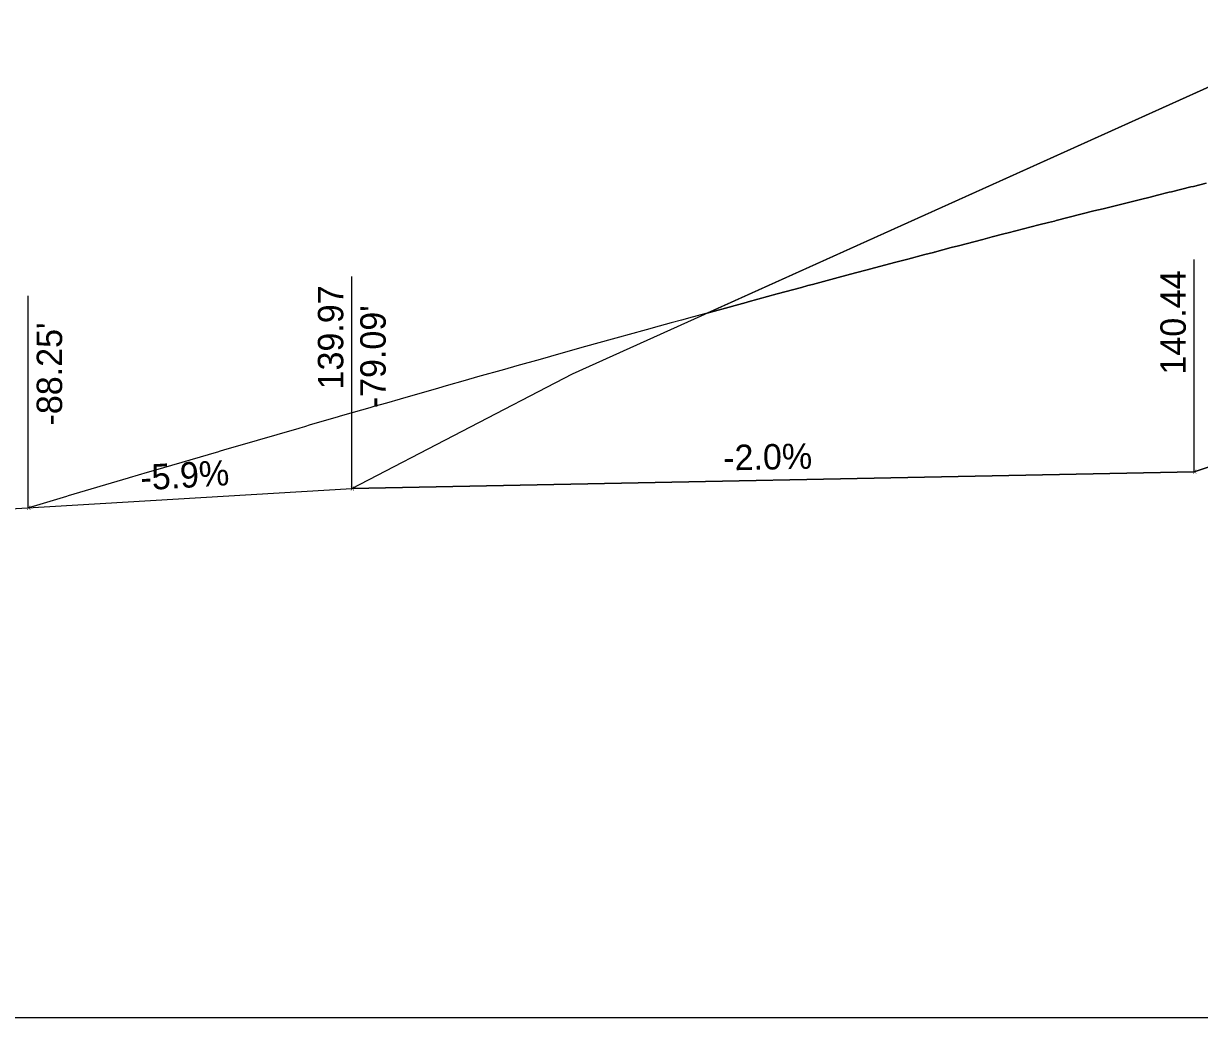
# Model space of a CAD drawing. Extents: x -26 to 4403, y -13 to 9578.
# Drawn here: x 3161.62 to 3194.9, y 8500 to 8528.12 of the extents above; entities that cross this region are included whole.
import ezdxf

# ---------------------------------------------------------------- set-up
doc = ezdxf.new("R2010")
doc.units = 0
for name, color, linetype in [('DTM_CONTOURS_MINOR', 7, 'Continuous'), ('DTM_X_GROUND', 7, 'Continuous'), ('X_PROFILES_1', 7, 'Continuous'), ('XS_CELL', 7, 'Continuous'), ('XS_M_SHAPES_EARTHWORK', 7, 'Continuous'), ('XS_P_GROUND', 7, 'Continuous'), ('XS_P_TX_CLEARZONE', 7, 'Continuous'), ('XS_P_TX_FS_BS', 7, 'Continuous')]:
    doc.layers.add(name, color=color, linetype=linetype)

msp = doc.modelspace()

# ---------------------------------------------------------------- linework, layer by layer
at = {"layer": 'DTM_X_GROUND'}
msp.add_lwpolyline([(3153.808, 8513.95), (3170.909, 8514.966), (3177.153, 8518.209), (3197.118, 8527.209), (3198.789, 8527.5), (3201.713, 8527.882), (3210.312, 8528.066), (3213.777, 8528.123), (3216.864, 8528.039), (3224.572, 8527.826), (3225.877, 8527.605), (3229.562, 8526.928), (3236.992, 8522.323), (3249.998, 8515.154), (3250, 8515.153), (3250.751, 8515.018), (3252.885, 8514.328), (3255.752, 8514.055), (3262.783, 8513.146), (3270.679, 8512.757), (3325.754, 8511.013), (3363.759, 8510.776), (3378.096, 8510.765), (3400, 8511.068)], dxfattribs=at)
at = {"layer": 'XS_CELL'}
msp.add_line((3000, 8500), (3250, 8500), dxfattribs=at)
at = {"layer": 'XS_M_SHAPES_EARTHWORK'}
msp.add_lwpolyline([(3170.909, 8514.966), (3177.153, 8518.209), (3197.118, 8527.209), (3198.789, 8527.5), (3201.713, 8527.882), (3210.312, 8528.066), (3213.777, 8528.123), (3216.864, 8528.039), (3224.572, 8527.826), (3225.877, 8527.605), (3229.562, 8526.928), (3231.967, 8525.437), (3225.826, 8525.314), (3220, 8523.858), (3194.753, 8515.443)], close=True, dxfattribs=at)
at = {"layer": 'XS_P_GROUND'}
msp.add_line((3180.966, 8519.928), (3181.279, 8520.011), dxfattribs=at)
for points in [[(3229.815, 8526.77), (3229.562, 8526.928), (3225.877, 8527.605), (3224.572, 8527.826), (3216.864, 8528.039), (3213.777, 8528.123), (3210.312, 8528.066), (3201.713, 8527.882), (3198.789, 8527.5), (3197.118, 8527.209), (3180.966, 8519.928)], [(3194.753, 8515.443), (3220, 8523.858), (3220, 8523.858), (3220, 8523.858), (3232, 8526.858)], [(3195.088, 8523.603), (3194.732, 8523.516), (3194.659, 8523.499), (3194.104, 8523.362), (3194.046, 8523.349), (3193.671, 8523.255), (3193.641, 8523.248), (3193.468, 8523.205), (3193.266, 8523.158), (3192.171, 8522.882), (3191.914, 8522.82), (3190.845, 8522.547), (3190.796, 8522.535), (3190.628, 8522.491), (3190.354, 8522.425), (3189.483, 8522.198), (3189.363, 8522.169), (3189.037, 8522.083), (3188.765, 8522.016), (3188.083, 8521.836), (3187.869, 8521.783), (3187.396, 8521.656), (3187.387, 8521.654), (3187.369, 8521.649), (3187.128, 8521.589), (3186.645, 8521.459), (3186.308, 8521.374), (3185.7, 8521.209), (3185.496, 8521.157), (3185.164, 8521.067), (3184.672, 8520.94), (3183.945, 8520.741), (3183.813, 8520.707), (3183.639, 8520.658), (3182.952, 8520.478), (3182.127, 8520.249), (3182.097, 8520.241), (3182.066, 8520.233), (3181.279, 8520.011), (3180.442, 8519.789), (3180.347, 8519.762), (3180.241, 8519.733), (3179.95, 8519.651), (3179.61, 8519.559), (3179.237, 8519.453), (3178.763, 8519.325), (3178.485, 8519.25), (3178.281, 8519.191), (3177.527, 8518.985), (3177.027, 8518.841), (3176.532, 8518.705), (3176.24, 8518.62), (3175.578, 8518.437), (3175.228, 8518.335), (3174.467, 8518.123), (3174.114, 8518.019), (3173.582, 8517.87), (3173.361, 8517.805), (3172.274, 8517.499), (3171.892, 8517.385), (3171.536, 8517.284), (3171.423, 8517.251), (3170.642, 8517.028), (3170.426, 8516.964), (3169.735, 8516.766), (3169.569, 8516.716), (3169.438, 8516.678), (3169.408, 8516.669), (3167.607, 8516.149), (3167.308, 8516.059), (3167.156, 8516.015), (3167.134, 8516.008), (3165.29, 8515.469), (3165.119, 8515.417), (3164.613, 8515.269), (3164.576, 8515.257), (3162.879, 8514.757), (3162.832, 8514.742), (3161.888, 8514.462), (3161.885, 8514.461), (3161.752, 8514.422)], [(3181.279, 8520.011), (3182.066, 8520.233), (3182.097, 8520.241), (3182.127, 8520.249), (3182.952, 8520.478), (3183.639, 8520.658), (3183.813, 8520.707), (3183.945, 8520.741), (3184.672, 8520.94), (3185.164, 8521.067), (3185.496, 8521.157), (3185.7, 8521.209), (3186.308, 8521.374), (3186.645, 8521.459), (3187.128, 8521.589), (3187.369, 8521.649), (3187.396, 8521.656), (3187.869, 8521.783), (3188.083, 8521.836), (3188.765, 8522.016), (3189.037, 8522.083), (3189.363, 8522.169), (3189.483, 8522.198), (3190.354, 8522.425), (3190.628, 8522.491), (3190.796, 8522.535), (3190.845, 8522.547), (3191.914, 8522.82), (3192.171, 8522.882), (3193.266, 8523.158), (3193.468, 8523.205), (3193.641, 8523.248), (3193.671, 8523.255), (3194.046, 8523.349), (3194.104, 8523.362), (3194.659, 8523.499), (3194.732, 8523.516), (3195.088, 8523.603)], [(3170.909, 8514.966), (3170.909, 8514.966), (3194.753, 8515.443)]]:
    msp.add_lwpolyline(points, dxfattribs=at)
at = {"layer": 'XS_P_TX_CLEARZONE'}
for p, q in [((3194.753, 8515.443), (3194.753, 8521.443)), ((3194.753, 8515.443), (3194.753, 8521.443)), ((3194.753, 8515.443), (3194.753, 8521.443)), ((3194.753, 8515.443), (3194.753, 8521.443)), ((3194.753, 8515.443), (3194.753, 8521.443)), ((3194.753, 8515.443), (3194.753, 8521.443)), ((3170.909, 8514.966), (3170.909, 8520.966)), ((3170.909, 8514.966), (3170.909, 8520.966)), ((3170.909, 8514.966), (3170.909, 8520.966)), ((3161.752, 8514.422), (3161.752, 8520.422)), ((3161.752, 8514.422), (3161.752, 8520.422)), ((3161.752, 8514.422), (3161.752, 8520.422))]:
    msp.add_line(p, q, dxfattribs=at)

# ---------------------------------------------------------------- texts
at = {"layer": 'DTM_CONTOURS_MINOR'}
msp.add_text('X', height=0.12, dxfattribs=at).set_placement((3170.87, 8514.906))
at = {"layer": 'X_PROFILES_1'}
for p in [(3194.714, 8515.383), (3161.712, 8514.362)]:
    msp.add_text('X', height=0.12, dxfattribs=at).set_placement(p)
at = {"layer": 'XS_P_TX_CLEARZONE'}
for s, p in [('140.44', (3194.513, 8518.191)), ('140.44', (3194.513, 8518.191)), ('140.44', (3194.513, 8518.191)), ('140.44', (3194.513, 8518.191)), ('140.44', (3194.513, 8518.191)), ('140.44', (3194.513, 8518.191)), ('139.97', (3170.669, 8517.77)), ('139.97', (3170.669, 8517.77)), ('139.97', (3170.669, 8517.77)), ("-79.09'", (3171.869, 8517.237)), ("-79.09'", (3171.869, 8517.237)), ("-79.09'", (3171.869, 8517.237)), ("-88.25'", (3162.712, 8516.75)), ("-88.25'", (3162.712, 8516.75)), ("-88.25'", (3162.712, 8516.75))]:
    msp.add_text(s, height=0.72, rotation=90, dxfattribs=at).set_placement(p)
at = {"layer": 'XS_P_TX_FS_BS'}
for s, rotation, p in [('-2.0%', 1.1458, (3181.429, 8515.477)), ('-2.0%', 1.1458, (3181.429, 8515.477)), ('-2.0%', 1.1458, (3181.429, 8515.477)), ('-5.9%', 3.4029, (3164.947, 8514.912)), ('-5.9%', 3.4029, (3164.947, 8514.912)), ('-5.9%', 3.4029, (3164.947, 8514.912))]:
    msp.add_text(s, height=0.72, rotation=rotation, dxfattribs=at).set_placement(p)

doc.saveas('drawing.dxf')
